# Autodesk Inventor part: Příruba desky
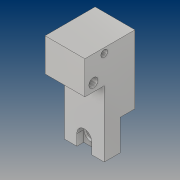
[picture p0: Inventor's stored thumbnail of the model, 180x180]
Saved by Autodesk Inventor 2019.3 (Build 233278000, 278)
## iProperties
Created: 2019-01
Part Number: Příruba desky
Material: Hliník 6061-AHC
Document SubType Name: Modeling
Designer: B-hon
Density: 2.7 g/cm^3
Appearance: Hliník – tmavý
Author: B-hon
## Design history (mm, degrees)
sketch "Náčrt1"
  geometry: L1 (-32.5, 40)-(32.5, 40); L2 (32.5, 40)-(32.5, -40); L3 (32.5, -40)-(-32.5, -40); L4 (-32.5, -40)-(-32.5, 40); L5 (-32.5, 40)-(32.5, -40); L6 (32.5, 40)-(-32.5, -40); 1 further point
  constraints: 12 end point, 2 midpoint, 2 parallel, 1 horizontal, 1 perpendicular
  dimensions: "d0" = 65 distance of L2.end L3.end; "d1" = 80 distance of L1.end L2.end
extrude "Vysunutí1" new body sketch "Náčrt1" distance "d2" = 26; taper "d3" = 0 deg
sketch "Náčrt2"
  geometry: L1 (-44.381, 28)-(47.748, 28); L2 (47.748, 28)-(47.748, 22); L3 (47.748, 22)-(-44.381, 22); L4 (-44.381, 22)-(-44.381, 28); L5 (-44.381, 28)-(47.748, 22); L6 (47.748, 28)-(-44.381, 22); L7 (-32.5, -40)-(32.5, -40) reference; L8 (-38.512, 18)-(43.239, 18); L9 (43.239, 18)-(43.239, -45.522); L10 (43.239, -45.522)-(-38.512, -45.522); L11 (-38.512, -45.522)-(-38.512, 18); L12 (-32.5, 40)-(-32.5, -40) reference; 2 further points
  constraints: 20 end point, 4 parallel, 2 horizontal, 2 midpoint, 2 perpendicular
  dimensions: "d4" = 6 distance of L1.end L2.end; "d5" = 65 distance from line of L7 point (1.683, 25); "d6" = 7 distance from line of L8 point (1.683, 25)
extrude "Vysunutí2" cut sketch "Náčrt2" distance "d10" = 14; taper "d11" = 0 deg
sketch "Náčrt3"
  geometry: L1 (-39.607, 44.84)-(-17.5, 44.84); L2 (-17.5, 44.84)-(-17.5, 11.926); L3 (-17.5, 11.926)-(-39.607, 11.926); L4 (-39.607, 11.926)-(-39.607, 44.84); L5 (17.5, 44.045)-(36.686, 44.045); L6 (36.686, 44.045)-(36.686, 9.931); L7 (36.686, 9.931)-(17.5, 9.931); L8 (17.5, 9.931)-(17.5, 44.045); L9 (-32.5, 40)-(-32.5, 18) reference; 1 further point
  constraints: 16 end point, 4 parallel, 2 horizontal, 2 perpendicular
  dimensions: "d12" = 35 distance between parallel lines of L8 L2; "d13" = 15 distance between parallel lines of L9 L2
extrude "Vysunutí3" cut sketch "Náčrt3" distance "d14" = 14; taper "d15" = 0 deg
sketch "Náčrt4"
  geometry: L1 (26, -58)-(14, -58) reference; L2 (0, 0)-(0, 22) reference; 2 further points
  dimensions: "d16" = 65 distance from line of L1 point (4.5, 7); "d17" = 4.5 distance from line of L2 point (4.5, 7)
hole "Díra1" sketch "Náčrt4" at (4.5, 7) diameter "d18" = 8; stored, may be unused: countersink angle "d22" = 90 deg, drill point angle "d24" = 118 deg; dims "d19" = 6, "d20" = 11, "d21" = 6.8, "d23" = 8
node "Upravit přímo1"
sketch "Náčrt6"
  geometry: L1 (32.5, -40)-(-32.5, -40) reference; C1 r 6.5 at (0, -30); 1 further point
  constraints: 1 centre point
  dimensions: "d39" = 13 diameter of C1; "d40" = 10 distance from line of L1 C1.centre
extrude "Vysunutí4" cut sketch "Náčrt6" distance "d41" = 8; taper "d42" = 0 deg
sketch "Náčrt7"
  geometry: L1 (-6.5, -61.308)-(6.5, -61.308); L2 (6.5, -61.308)-(6.5, -30.361); L3 (6.5, -30.361)-(-6.5, -30.361); L4 (-6.5, -30.361)-(-6.5, -61.308); L5 (-6.5, -61.308)-(6.5, -30.361); L6 (6.5, -61.308)-(-6.5, -30.361); 2 further points
  constraints: 12 end point, 2 midpoint, 2 parallel, 1 horizontal, 1 perpendicular
  dimensions: "d43" = 13 distance of L3.end L2.end
extrude "Vysunutí5" cut sketch "Náčrt7" distance "d44" = 6; taper "d45" = 0 deg
node "Upravit přímo2"
sketch "Náčrt10"
  geometry: L1 (-48.128, 53.565)-(-17.5, 53.565); L2 (-17.5, 53.565)-(-17.5, -46.218); L3 (-17.5, -46.218)-(-48.128, -46.218); L4 (-48.128, -46.218)-(-48.128, 53.565); L5 (17.5, 54.3)-(38.723, 54.3); L6 (38.723, 54.3)-(38.723, -45.483); L7 (38.723, -45.483)-(17.5, -45.483); L8 (17.5, -45.483)-(17.5, 54.3); L9 (-17.5, 45)-(-17.5, 18) reference; L10 (17.5, 18)-(17.5, 45) reference; 1 further point
  constraints: 16 end point, 4 parallel, 2 horizontal, 2 perpendicular
  dimensions: "d67" = 0 distance between parallel lines of L9 L2; "d68" = 0 distance between parallel lines of L8 L10
extrude "Vysunutí6" cut sketch "Náčrt10" distance "d69" = 15; taper "d70" = 0 deg
node "Upravit přímo4"
sketch "Náčrt12"
  geometry: L1 (12, 87)-(12, 0) reference; L2 (-17, 87)-(12, 87) reference; 2 further points
  dimensions: "d89" = 12 distance from line of L1 point (0, 82.5); "d90" = 4.5 distance from line of L2 point (0, 82.5)
hole "Díra6" sketch "Náčrt12" at (0, 82.5) diameter "d91" = 6; stored, may be unused: countersink angle "d95" = 90 deg, drill point angle "d97" = 118 deg; dims "d92" = 16, "d93" = 15, "d94" = 9, "d96" = 13
node "Upravit přímo6"
sketch "Náčrt13"
  geometry: L1 (0, 58)-(0, 87) reference; L2 (0, 87)-(35, 87); L3 (35, 87)-(35, 27); L4 (35, 27)-(0, 27); L5 (0, 27)-(0, 87); L6 (35, 87)-(0, 87) reference; 1 further point
  constraints: 8 end point, 2 parallel, 1 horizontal, 1 perpendicular, 1 point on line
  dimensions: "d101" = 35 distance of L3.end L4.end; "d102" = 60 distance of L2.end L3.end; "d103" = 60 distance between parallel lines of L4 L6
extrude "Vysunutí7" join sketch "Náčrt13" distance "d104" = 13; taper "d105" = 0 deg
sketch "Náčrt14"
  geometry: L1 (0, 27)-(35, 27) reference; L2 (0, 87)-(0, 27) reference; 4 further points
  constraints: 1 horizontal alignment
  dimensions: "d106" = 7 distance from line of L1 point (7, 34); "d107" = 7 distance from line of L2 point (7, 34) (= d106); "d108" = 21 distance of point (7, 34) point (28, 34); "d109" = 10.5 horizontal distance of point (28, 34) point (17.5, 79); "d110" = 52 distance from line of L1 point (17.5, 79)
hole "Díra7" sketch "Náčrt14" at (7, 34), (28, 34), (17.5, 79) diameter "d111" = 4.134; stored, may be unused: countersink angle "d115" = 90 deg, drill point angle "d117" = 118 deg; dims "d112" = 15, "d113" = 4, "d114" = 2, "d116" = 20
chamfer "Zkosení1" distance "d118" = 0.5; stored, may be unused: second distance "d119" = 2, angle "d120" = 45 deg
node "Těleso1"
feature "Posunout1" dims "d27" = 5
feature "Posunout2" dims "d48" = 3
feature "Posunout4" dims "d76" = 2
feature "Posunout6" dims "d100" = 2
other parameters: "d25" = 0, "d26" = 0, "d46" = 0, "d47" = 0, "d74" = 0, "d75" = 0, "d98" = 0, "d99" = 0
